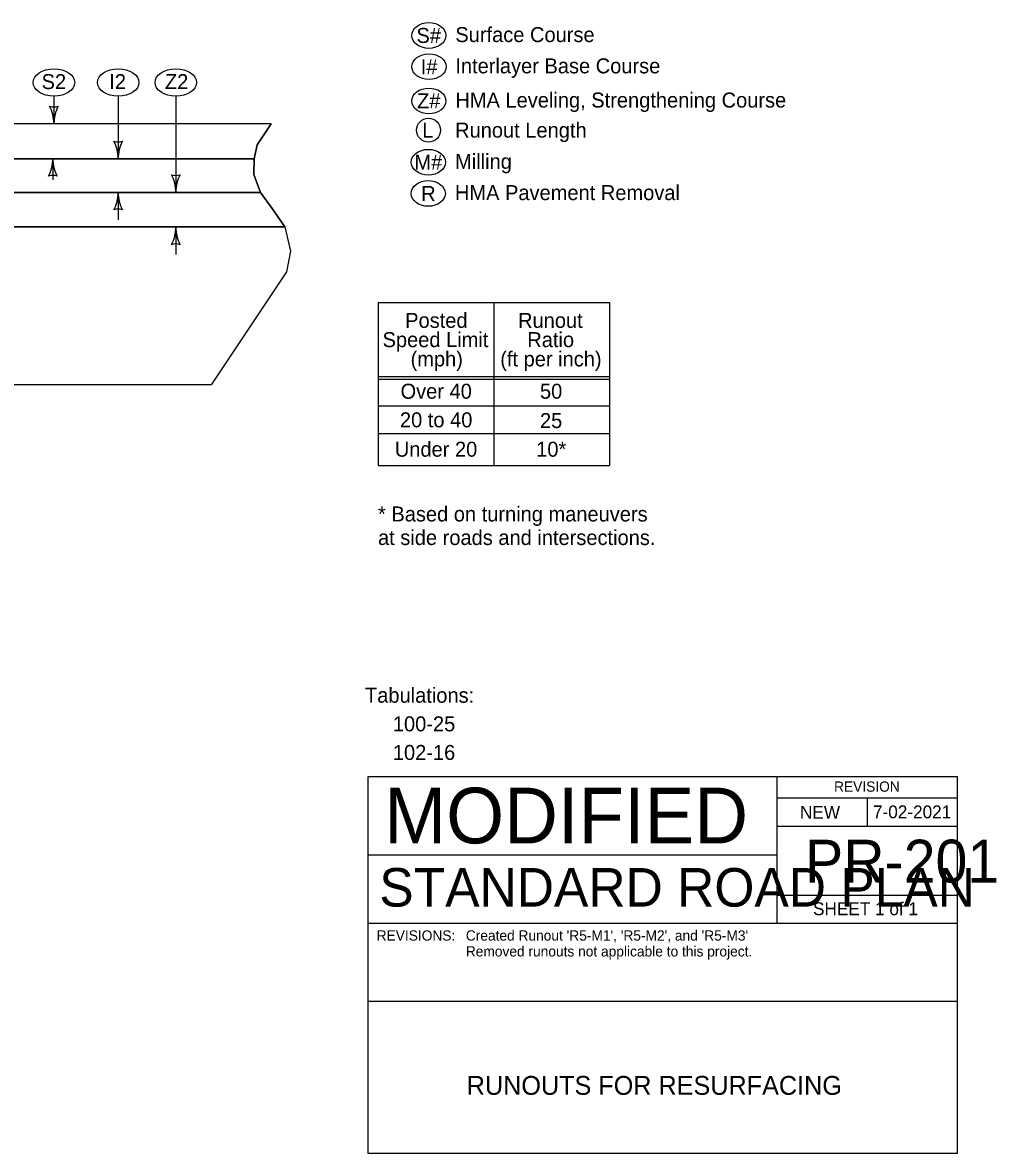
# Model space of a CAD drawing. Extents: x 10133 to 81668, y 2218 to 11018.
# Drawn here: x 12176 to 13313, y 5441 to 6761 of the extents above; entities that cross this region are included whole.
import ezdxf

# ---------------------------------------------------------------- set-up
doc = ezdxf.new("R2010")
doc.units = 0
for name, color, linetype in [('dsnNonPlotable', 7, 'Continuous'), ('dsnStdBlock', 7, 'Continuous'), ('dsnStdBlockModified', 7, 'Continuous'), ('dsnStdBlockNotModified', 7, 'Continuous'), ('dsnStdBorder', 7, 'Continuous')]:
    doc.layers.add(name, color=color, linetype=linetype)

msp = doc.modelspace()

# ---------------------------------------------------------------- linework, layer by layer
at = {"layer": 'dsnNonPlotable'}
for points in [[(12446.5, 6601.8), (12449.8, 6617.8), (12466.5, 6642.4), (12138.6, 6642.4), (11103.6, 6539.1), (10496.6, 6539.1), (10486.7, 6519.2), (10483.7, 6498.5), (11103.6, 6498.5), (11343.4, 6522.4), (12138.6, 6601.8)], [(11343.4, 6522.4), (11737.8, 6522.4), (12138.6, 6562.4), (12454, 6562.4), (12446.2, 6583.3), (12446.5, 6601.8), (12138.6, 6601.8), (11343.4, 6522.4)], [(12242.3, 6521.8), (12482.2, 6522.4), (12467.4, 6543.7), (12454, 6562.4), (12138.6, 6562.4), (12138.6, 6562.4), (11737.8, 6522.4)]]:
    msp.add_lwpolyline(points, close=True, dxfattribs=at)
at = {"layer": 'dsnStdBlock'}
for p, q in [((12212.7, 6674.8), (12212.7, 6642.8)), ((12287.7, 6674.8), (12287.7, 6601.8)), ((12355, 6674.8), (12355, 6562.4)), ((12466.5, 6642.4), (12138.6, 6642.4)), ((12446.5, 6601.8), (12138.6, 6601.8)), ((12211.5, 6601.8), (12211.5, 6577.2)), ((12454, 6562.4), (12138.6, 6562.4)), ((12287.6, 6562.4), (12287.6, 6530.4)), ((12482.2, 6522.4), (10488.3, 6522.4)), ((12355, 6521.8), (12355, 6489.8)), ((12591.1, 6433.8), (12591.1, 6243.5)), ((12591.1, 6433.8), (12861.4, 6433.8)), ((12726.3, 6433.8), (12726.3, 6243.5)), ((12861.4, 6433.8), (12861.4, 6243.5)), ((12396.4, 6337.9), (10496.6, 6337.9)), ((12591.1, 6347.4), (12861.4, 6347.4)), ((12591.1, 6344.4), (12861.4, 6344.4)), ((12591.1, 6313.3), (12861.4, 6313.3)), ((12591.1, 6280.8), (12861.4, 6280.8)), ((12591.1, 6243.5), (12861.4, 6243.5))]:
    msp.add_line(p, q, dxfattribs=at)
msp.add_lwpolyline([(12466.5, 6642.4), (12449.8, 6617.8), (12446.5, 6601.8), (12446.2, 6583.3), (12454, 6562.4), (12467.4, 6543.7), (12482.2, 6522.4), (12488.8, 6493.7), (12484.3, 6469.8), (12396.4, 6337.9)], dxfattribs=at)
msp.add_circle((12650.1, 6635.1), 14, dxfattribs=at)
for centre, radius, start, end in [((12212.7, 6679), 16.7, 252.2666, 287.7334), ((12169.5, 6642.8), 43.2, 0, 28.0725), ((12255.9, 6642.8), 43.2, 151.9275, 180), ((12287.7, 6638), 16.7, 252.2666, 287.7334), ((12244.5, 6601.8), 43.2, 0, 28.0725), ((12330.9, 6601.8), 43.2, 151.9275, 180), ((12168.3, 6601.8), 43.2, 331.9275, 0), ((12254.6, 6601.8), 43.2, 180, 208.0725), ((12211.5, 6565.6), 16.7, 72.2666, 107.7334), ((12355, 6599), 16.7, 252.2666, 287.7334), ((12311.8, 6562.8), 43.2, 0, 28.0725), ((12398.1, 6562.8), 43.2, 151.9275, 180), ((12244.5, 6562.4), 43.2, 331.9275, 0), ((12330.8, 6562.4), 43.2, 180, 208.0725), ((12287.6, 6526.2), 16.7, 72.2666, 107.7334), ((12311.8, 6521.8), 43.2, 331.9275, 0), ((12398.2, 6521.8), 43.2, 180, 208.0725), ((12355, 6485.5), 16.7, 72.2666, 107.7334)]:
    msp.add_arc(centre, radius, start, end, dxfattribs=at)
for centre, major_axis, ratio in [((12650.4, 6745.6), (-20, 0), 0.749963), ((12650.7, 6709.2), (-20, 0), 0.749963), ((12212.7, 6690.8), (24.3, 0), 0.658717), ((12287.7, 6690.8), (24.3, 0), 0.658717), ((12355, 6690.8), (24.3, 0), 0.658717), ((12650.4, 6669.2), (-20, 0), 0.749963), ((12649.9, 6597.7), (-20, 0), 0.749963), ((12649.7, 6561.2), (-20, 0), 0.749963)]:
    msp.add_ellipse(centre, major_axis=major_axis, ratio=ratio, dxfattribs=at)
at = {"layer": 'dsnStdBlockModified'}
for p, q in [((13056.6, 5880.6), (13056.6, 5789.3)), ((13056.6, 5855.7), (13267.5, 5855.7)), ((13162.1, 5855.7), (13162.1, 5822.5)), ((13056.6, 5822.5), (13267.5, 5822.5)), ((13056.6, 5789.3), (13056.6, 5709.3)), ((13267.5, 5741.5), (13056.6, 5741.5)), ((12579.5, 5709.3), (13267.5, 5709.3))]:
    msp.add_line(p, q, dxfattribs=at)
msp.add_lwpolyline([(12579.5, 5880.6), (13267.5, 5880.6), (13267.5, 5440.6), (12579.5, 5440.6)], close=True, dxfattribs=at)
at = {"layer": 'dsnStdBorder'}
for p, q in [((12579.5, 5789.3), (13056.6, 5789.3)), ((12579.5, 5618.3), (13267.5, 5618.3))]:
    msp.add_line(p, q, dxfattribs=at)

# ---------------------------------------------------------------- texts
at = {"layer": 'dsnStdBlock'}
for s, p in [('Tabulations:', (12575.9, 5966.7)), ('     100-25', (12575.9, 5933.3)), ('     102-16', (12575.9, 5899.9))]:
    msp.add_text(s, height=17.5, dxfattribs=at).set_placement(p)
at = {"layer": 'dsnStdBlockModified'}
for s, height, p in [('REVISION', 12, (13123.6, 5862.8)), ('MODIFIED', 65, (12598.3, 5802.5)), ('NEW', 15, (13083.8, 5831.3)), ('7-02-2021', 15, (13169, 5831.8)), ('PR-201', 50, (13089.7, 5756.8)), ('STANDARD ROAD PLAN', 45.001, (12592.6, 5728.7)), ('SHEET 1 of 1', 15, (13099, 5718.7)), ('RUNOUTS FOR RESURFACING', 22, (12694.7, 5509))]:
    msp.add_text(s, height=height, dxfattribs=at).set_placement(p)
at = {"layer": 'dsnStdBlockNotModified'}
for s, p in [('S#', (12636, 6736.9)), ('Surface Course', (12681.4, 6737.9)), ('Interlayer Base Course', (12681.4, 6701.4)), ('I#', (12641, 6700.4)), ('S2', (12198.3, 6683)), ('I2', (12277.3, 6683)), ('Z2', (12342.2, 6683)), ('HMA Leveling, Strengthening Course', (12681.4, 6661.5)), ('Z#', (12636.7, 6660.5)), ('L', (12642.8, 6626.4)), ('Runout Length', (12681.1, 6626.4)), ('M#', (12633.6, 6588.9)), ('Milling', (12681.1, 6589.9)), ('R', (12641.5, 6552.4)), ('HMA Pavement Removal', (12680.9, 6553.4)), ('Posted', (12622.8, 6404.3)), ('Runout', (12754.6, 6404.3)), ('Speed Limit', (12596.4, 6381.8)), ('Ratio', (12765.4, 6381.8)), ('(mph)', (12629.1, 6359.3)), ('(ft per inch)', (12733.8, 6359.3)), ('Over 40', (12617.4, 6321.6)), ('50', (12780.2, 6321.6)), ('20 to 40', (12616.7, 6288.2)), ('25', (12780.2, 6287.3)), ('Under 20', (12610.7, 6253.9)), ('10*', (12775.8, 6253.9)), ('* Based on turning maneuvers ', (12591.1, 6178.3)), ('at side roads and intersections.', (12591.1, 6150.8))]:
    msp.add_text(s, height=17.5, dxfattribs=at).set_placement(p)
at = {"layer": 'dsnStdBorder'}
for s, p in [('REVISIONS:', (12589.5, 5689)), ("Created Runout 'R5-M1', 'R5-M2', and 'R5-M3'", (12693.6, 5689)), ('Removed runouts not applicable to this project.', (12693.6, 5670.5))]:
    msp.add_text(s, height=12, dxfattribs=at).set_placement(p)

doc.saveas('drawing.dxf')
